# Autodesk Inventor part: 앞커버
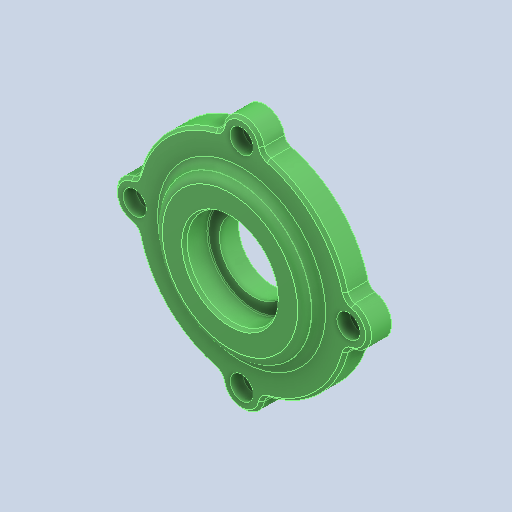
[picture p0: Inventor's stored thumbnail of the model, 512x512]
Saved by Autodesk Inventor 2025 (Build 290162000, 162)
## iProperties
Created: 2024-08
Part Number: 앞커버
Material: 알루미늄 6061
Document SubType Name: Modeling
Designer: samsung
Density: 2.71 g/cm^3
Appearance: 기본값
Company: 한국ATC센터
Author: jhkim
Sending System: Autodesk Inventor 2025
Preprocessor: ST-DEVELOPER v20
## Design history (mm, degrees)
feature "솔리드1"
node "솔리드2"
